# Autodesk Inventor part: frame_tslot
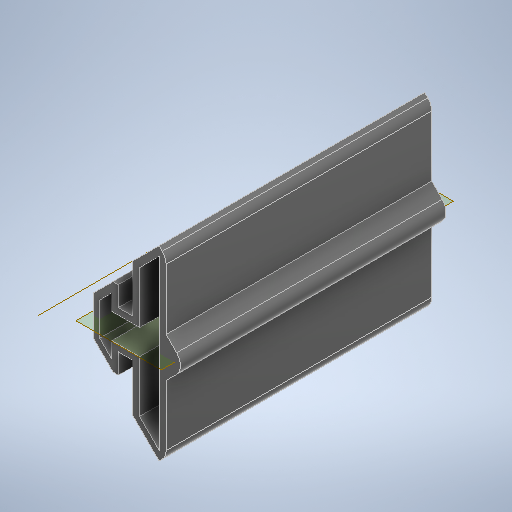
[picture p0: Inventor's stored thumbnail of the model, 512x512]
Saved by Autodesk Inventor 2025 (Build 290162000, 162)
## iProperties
Created: 2026-03
Part Number: frame_tslot
Material: Plastica ABS
Document SubType Name: Modeling
Designer: R5800u
Density: 1.06 g/cm^3
Appearance: Liscia - Nero
Author: R5800u
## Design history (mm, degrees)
sketch "Schizzo1"
  geometry: L1 (7.61, 290.16)-(7.91, 289.64) reference; L2 (7.91, 289.64)-(7.61, 289.121) reference; L3 (7.61, 289.121)-(7.61, 286.701) reference; L4 (7.61, 286.701)-(4.549, 283.64) reference; L5 (4.549, 283.64)-(3.61, 283.64) reference; L6 (3.61, 283.64)-(3.61, 286.64) reference; L7 (3.61, 286.64)-(1.91, 286.64) reference; L8 (1.61, 286.34)-(1.61, 280.64) reference; L9 (2.61, 279.64)-(8.31, 279.64) reference; L10 (8.61, 279.94)-(8.61, 281.64) reference; L11 (8.61, 281.64)-(5.61, 281.64) reference; L12 (5.61, 281.64)-(5.61, 282.58) reference; L13 (5.61, 282.58)-(8.67, 285.64) reference; L14 (8.67, 285.64)-(11.09, 285.64) reference; L15 (11.09, 285.64)-(11.61, 285.94) reference; L16 (11.61, 285.94)-(12.129, 285.64) reference; L17 (12.129, 285.64)-(14.549, 285.64) reference; L18 (14.549, 285.64)-(17.61, 282.58) reference; L19 (17.61, 282.58)-(17.61, 281.64) reference; L20 (17.61, 281.64)-(14.61, 281.64) reference; L21 (14.61, 281.64)-(14.61, 279.94) reference; L22 (14.91, 279.64)-(20.61, 279.64) reference; L23 (21.61, 280.64)-(21.61, 286.34) reference; L24 (21.31, 286.64)-(19.61, 286.64) reference; L25 (19.61, 286.64)-(19.61, 283.64) reference; L26 (19.61, 283.64)-(18.67, 283.64) reference; L27 (18.67, 283.64)-(15.61, 286.701) reference; L28 (15.61, 286.701)-(15.61, 289.121) reference; L29 (15.61, 289.121)-(15.31, 289.64) reference; L30 (15.31, 289.64)-(15.61, 290.16) reference; L31 (15.61, 290.16)-(15.61, 292.58) reference; L32 (15.61, 292.58)-(18.67, 295.64) reference; L33 (18.67, 295.64)-(19.61, 295.64) reference; L34 (19.61, 295.64)-(19.61, 292.64) reference; L35 (19.61, 292.64)-(21.31, 292.64) reference; L36 (21.61, 292.94)-(21.61, 298.64) reference; L37 (20.61, 299.64)-(14.91, 299.64) reference; L38 (14.61, 299.34)-(14.61, 297.64) reference; L39 (14.61, 297.64)-(17.61, 297.64) reference; L40 (17.61, 297.64)-(17.61, 296.701) reference; L41 (17.61, 296.701)-(14.549, 293.64) reference; L42 (14.549, 293.64)-(12.129, 293.64) reference; L43 (12.129, 293.64)-(11.61, 293.34) reference; L44 (11.61, 293.34)-(11.09, 293.64) reference; L45 (11.09, 293.64)-(8.67, 293.64) reference; L46 (8.67, 293.64)-(5.61, 296.701) reference; L47 (5.61, 296.701)-(5.61, 297.64) reference; L48 (5.61, 297.64)-(8.61, 297.64) reference; L49 (8.61, 297.64)-(8.61, 299.34) reference; L50 (8.31, 299.64)-(2.61, 299.64) reference; L51 (1.61, 298.64)-(1.61, 292.94) reference; L52 (1.91, 292.64)-(3.61, 292.64) reference; L53 (3.61, 292.64)-(3.61, 295.64) reference; L54 (3.61, 295.64)-(4.549, 295.64) reference; L55 (4.549, 295.64)-(7.61, 292.58) reference; L56 (7.61, 292.58)-(7.61, 290.16) reference; L57 (21.71, 298.64)-(21.71, 292.94); L58 (21.31, 292.54)-(19.51, 292.54); L59 (19.51, 292.54)-(19.51, 295.54); L60 (19.51, 295.54)-(18.712, 295.54); L61 (18.712, 295.54)-(15.71, 292.538); L62 (15.71, 292.538)-(15.71, 290.133); L63 (15.71, 289.148)-(15.71, 286.742); L64 (15.71, 286.742)-(18.712, 283.74)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; C1 r 2.1 at (11.61, 289.64) reference; A1 r 0.3 centre (1.91, 286.34) between (1.91, 286.64) and (1.61, 286.34) reference; A2 r 1 centre (2.61, 280.64) between (1.61, 280.64) and (2.61, 279.64) reference; A3 r 0.3 centre (8.31, 279.94) between (8.31, 279.64) and (8.61, 279.94) reference; A4 r 0.3 centre (14.91, 279.94) between (14.61, 279.94) and (14.91, 279.64) reference; A5 r 1 centre (20.61, 280.64) between (20.61, 279.64) and (21.61, 280.64) reference; A6 r 0.3 centre (21.31, 286.34) between (21.61, 286.34) and (21.31, 286.64) reference; A7 r 0.3 centre (21.31, 292.94) between (21.31, 292.64) and (21.61, 292.94) reference; A8 r 1 centre (20.61, 298.64) between (21.61, 298.64) and (20.61, 299.64) reference; A9 r 0.3 centre (14.91, 299.34) between (14.91, 299.64) and (14.61, 299.34) reference; A10 r 0.3 centre (8.31, 299.34) between (8.61, 299.34) and (8.31, 299.64) reference; A11 r 1 centre (2.61, 298.64) between (2.61, 299.64) and (1.61, 298.64) reference; A12 r 0.3 centre (1.91, 292.94) between (1.61, 292.94) and (1.91, 292.64) reference; A13 r 0.4 centre (21.31, 286.34) between (21.71, 286.34) and (21.31, 286.74); A14 r 1.1 centre (20.61, 280.64) between (20.61, 279.54) and (21.71, 280.64); A15 r 0.4 centre (14.91, 279.94) between (14.51, 279.94) and (14.91, 279.54); A16 r 0.4 centre (8.31, 279.94) between (8.31, 279.54) and (8.71, 279.94); A17 r 1.1 centre (2.61, 280.64) between (1.51, 280.64) and (2.61, 279.54); A18 r 0.4 centre (1.91, 286.34) between (1.91, 286.74) and (1.51, 286.34); A19 r 0.4 centre (1.91, 292.94) between (1.51, 292.94) and (1.91, 292.54); A20 r 1.1 centre (2.61, 298.64) between (2.61, 299.74) and (1.51, 298.64); A21 r 0.4 centre (8.31, 299.34) between (8.71, 299.34) and (8.31, 299.74); A22 r 0.4 centre (14.91, 299.34) between (14.91, 299.74) and (14.51, 299.34); A23 r 1.1 centre (20.61, 298.64) between (21.71, 298.64) and (20.61, 299.74); 2 further points
  constraints: 126 end point, 22 point on circle, 11 centre point, 4 point on line, 3 vertical, 2 horizontal, 2 perpendicular, 1 midpoint, 63 other
  dimensions: "d0" = 0.1 distance between parallel lines of L36 L57; "d10" = 11 distance between parallel lines of L62 L117
extrude "Estrusione1" new body sketch "Schizzo1" distance "d1" = 40; taper "d2" = 0 deg
mirror "Speculare1"
feature "Svuotamento1" dims "d3" = 1
node "Piano di lavoro1"
node "Asse di lavoro1"
sketch "Schizzo2"
  geometry: L1 (26.71, 304.74)-(26.71, 274.54) reference; L2 (26.71, 302.619)-(25.649, 303.68); L3 (21.71, 299.74)-(26.71, 304.74) reference; 1 further point
  constraints: 2 end point, 2 point on line, 1 perpendicular
  dimensions: "d9" = 1.5 distance from line of L1.start L2
extrude "Estrusione2" cut sketch "Schizzo2" extent not by distance; stored distance "d7" = 0; taper "d8" = 0 deg
mirror "Speculare2"
sketch "Schizzo3"
  geometry: L1 (26.71, 276.662)-(26.71, 302.619) reference; L2 (26.71, 289.64)-(29.71, 289.64); L3 (29.71, 289.64)-(26.71, 292.64); L4 (29.71, 289.64)-(26.71, 286.64); 2 further points
  constraints: 6 end point, 1 horizontal, 1 midpoint, 1 point on line, 1 symmetric about line
  dimensions: "d11" = 3 distance of L2.start L2.end; "d12" = 3 distance from line of L2 L3.end
extrude "Estrusione3" join sketch "Schizzo3" stored distance "d13" = 3 (= d11); taper "d14" = 0 deg
fillet "Raccordo1" dims "d15" = 2
fillet "Raccordo2" dims "d16" = 2
node "Solido1"
node "Riferimento1"
